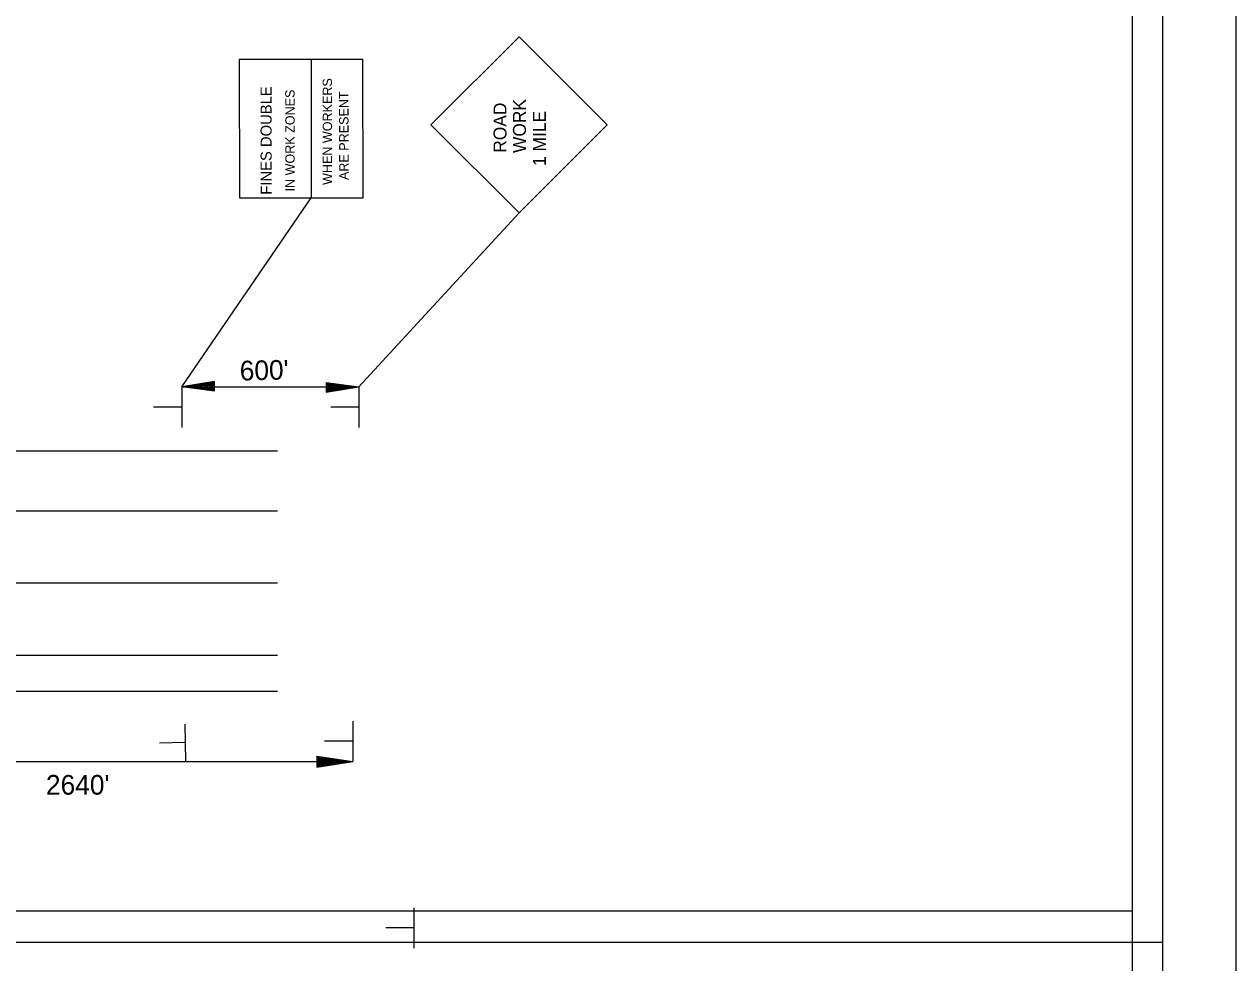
# Model space of a CAD drawing. Extents: x 1373222 to 1374279, y 380783 to 380996.
# Drawn here: x 1373476.4 to 1373555.3, y 380888.5 to 380949.6 of the extents above; entities that cross this region are included whole.
import ezdxf

# ---------------------------------------------------------------- set-up
doc = ezdxf.new("R2010")
doc.units = 0
for name, color, linetype in [('R_Border', 7, 'Continuous'), ('R_Border Plan-Plan', 7, 'Continuous'), ('R_Draft', 7, 'Continuous'), ('R_No Plot', 7, 'Continuous')]:
    doc.layers.add(name, color=color, linetype=linetype)

msp = doc.modelspace()

# ---------------------------------------------------------------- linework, layer by layer
at = {"layer": 'R_Border'}
msp.add_line((1373550.564, 380787.132), (1373550.564, 380992.592), dxfattribs=at)
at = {"layer": 'R_Border Plan-Plan'}
msp.add_line((1373234.384, 380889.862), (1373550.564, 380889.862), dxfattribs=at)
at = {"layer": 'R_Draft'}
for p, q in [((1373508.651, 380948.816), (1373502.916, 380943.081)), ((1373508.651, 380948.816), (1373514.38, 380943.081)), ((1373495.107, 380947.34), (1373495.114, 380938.335)), ((1373502.916, 380943.081), (1373508.651, 380937.347)), ((1373514.38, 380943.081), (1373508.651, 380937.347)), ((1373486.691, 380926.017), (1373495.114, 380938.335)), ((1373498.225, 380926.017), (1373508.651, 380937.347)), ((1373488.82, 380926.371), (1373486.691, 380926.017)), ((1373486.691, 380926.017), (1373498.225, 380926.017)), ((1373488.829, 380925.731), (1373486.691, 380926.017)), ((1373486.691, 380926.017), (1373486.691, 380923.376)), ((1373488.821, 380926.318), (1373487.048, 380926.023)), ((1373488.829, 380925.785), (1373487.048, 380926.023)), ((1373488.821, 380926.263), (1373487.414, 380926.028)), ((1373488.828, 380925.839), (1373487.414, 380926.028)), ((1373488.822, 380926.21), (1373487.77, 380926.034)), ((1373488.827, 380925.892), (1373487.77, 380926.034)), ((1373488.823, 380926.155), (1373488.132, 380926.04)), ((1373488.826, 380925.947), (1373488.132, 380926.04)), ((1373488.824, 380926.101), (1373488.487, 380926.046)), ((1373488.825, 380926.001), (1373488.487, 380926.046)), ((1373488.829, 380925.731), (1373488.82, 380926.371)), ((1373496.087, 380926.302), (1373498.225, 380926.017)), ((1373496.087, 380926.302), (1373496.097, 380925.662)), ((1373496.088, 380926.249), (1373497.869, 380926.01)), ((1373496.089, 380926.194), (1373497.502, 380926.005)), ((1373496.09, 380926.141), (1373497.147, 380925.999)), ((1373496.091, 380926.086), (1373496.785, 380925.993)), ((1373496.091, 380926.033), (1373496.429, 380925.987)), ((1373496.093, 380925.878), (1373496.785, 380925.993)), ((1373496.093, 380925.932), (1373496.429, 380925.987)), ((1373496.094, 380925.824), (1373497.147, 380925.999)), ((1373496.095, 380925.77), (1373497.502, 380926.005)), ((1373496.096, 380925.716), (1373497.869, 380926.01)), ((1373496.097, 380925.662), (1373498.225, 380926.017)), ((1373498.225, 380926.017), (1373498.225, 380923.376)), ((1373486.653, 380924.703), (1373484.851, 380924.703)), ((1373498.187, 380924.703), (1373496.385, 380924.703)), ((1373492.921, 380921.83), (1373407.818, 380921.83)), ((1373492.921, 380917.919), (1373407.818, 380917.919)), ((1373492.921, 380913.225), (1373407.818, 380913.225)), ((1373492.921, 380908.531), (1373407.818, 380908.531)), ((1373492.921, 380906.184), (1373407.818, 380906.184)), ((1373486.889, 380904.04), (1373486.927, 380901.641)), ((1373497.829, 380904.249), (1373497.829, 380901.608)), ((1373486.873, 380902.847), (1373485.234, 380902.82)), ((1373497.791, 380902.935), (1373495.989, 380902.935)), ((1373462.825, 380901.608), (1373497.829, 380901.608)), ((1373495.482, 380901.96), (1373497.829, 380901.608)), ((1373495.482, 380901.96), (1373495.482, 380901.256)), ((1373495.482, 380901.902), (1373497.437, 380901.608)), ((1373495.482, 380901.842), (1373497.033, 380901.608)), ((1373495.482, 380901.783), (1373496.643, 380901.608)), ((1373495.482, 380901.722), (1373496.245, 380901.608)), ((1373495.482, 380901.663), (1373495.852, 380901.608)), ((1373495.482, 380901.256), (1373497.829, 380901.608)), ((1373495.482, 380901.493), (1373496.245, 380901.608)), ((1373495.482, 380901.375), (1373497.033, 380901.608)), ((1373495.482, 380901.315), (1373497.437, 380901.608)), ((1373495.482, 380901.434), (1373496.643, 380901.608)), ((1373495.482, 380901.553), (1373495.852, 380901.608)), ((1373501.809, 380892.092), (1373501.809, 380889.452)), ((1373501.771, 380890.779), (1373499.969, 380890.779))]:
    msp.add_line(p, q, dxfattribs=at)
msp.add_lwpolyline([(1373490.445, 380938.331), (1373498.494, 380938.337), (1373498.486, 380947.343), (1373490.437, 380947.336)], close=True, dxfattribs=at)
at = {"layer": 'R_No Plot'}
for points in [[(1373221.977, 380996.487), (1373555.317, 380996.487), (1373555.317, 380783.15), (1373221.977, 380783.15)], [(1373548.564, 380891.862), (1373236.384, 380891.862), (1373236.384, 380990.592), (1373485.924, 380990.592), (1373485.924, 380980.712), (1373503.464, 380980.712), (1373527.564, 380980.712), (1373527.564, 380958.38), (1373548.564, 380958.38)], [(1373236.384, 380990.592), (1373485.924, 380990.592), (1373485.924, 380980.712), (1373503.464, 380980.712), (1373527.564, 380980.712), (1373527.564, 380958.38), (1373548.564, 380958.38), (1373548.564, 380789.132), (1373236.384, 380789.132)]]:
    msp.add_lwpolyline(points, close=True, dxfattribs=at)

# ---------------------------------------------------------------- texts
at = {"layer": 'R_Draft'}
for s, height, rotation, p in [('WHEN WORKERS', 0.61143, 90.05011, (1373496.479, 380939.169)), ('FINES DOUBLE', 0.72, 90.05011, (1373492.544, 380938.53)), ('IN WORK ZONES', 0.6113, 90.05011, (1373494.044, 380938.744)), ('ARE PRESENT', 0.61143, 90.05011, (1373497.55, 380939.488)), ('ROAD', 0.8448, 90.00045, (1373507.833, 380941.266)), ('WORK', 0.8445, 90.00004, (1373509.099, 380941.248)), ('1 MILE', 0.8448, 90.00045, (1373510.398, 380940.406)), ("600'", 1.28, 1.23039, (1373490.477, 380926.43)), ("2640'", 1.28, 360, (1373477.848, 380899.46))]:
    msp.add_text(s, height=height, rotation=rotation, dxfattribs=at).set_placement(p)

doc.saveas('drawing.dxf')
